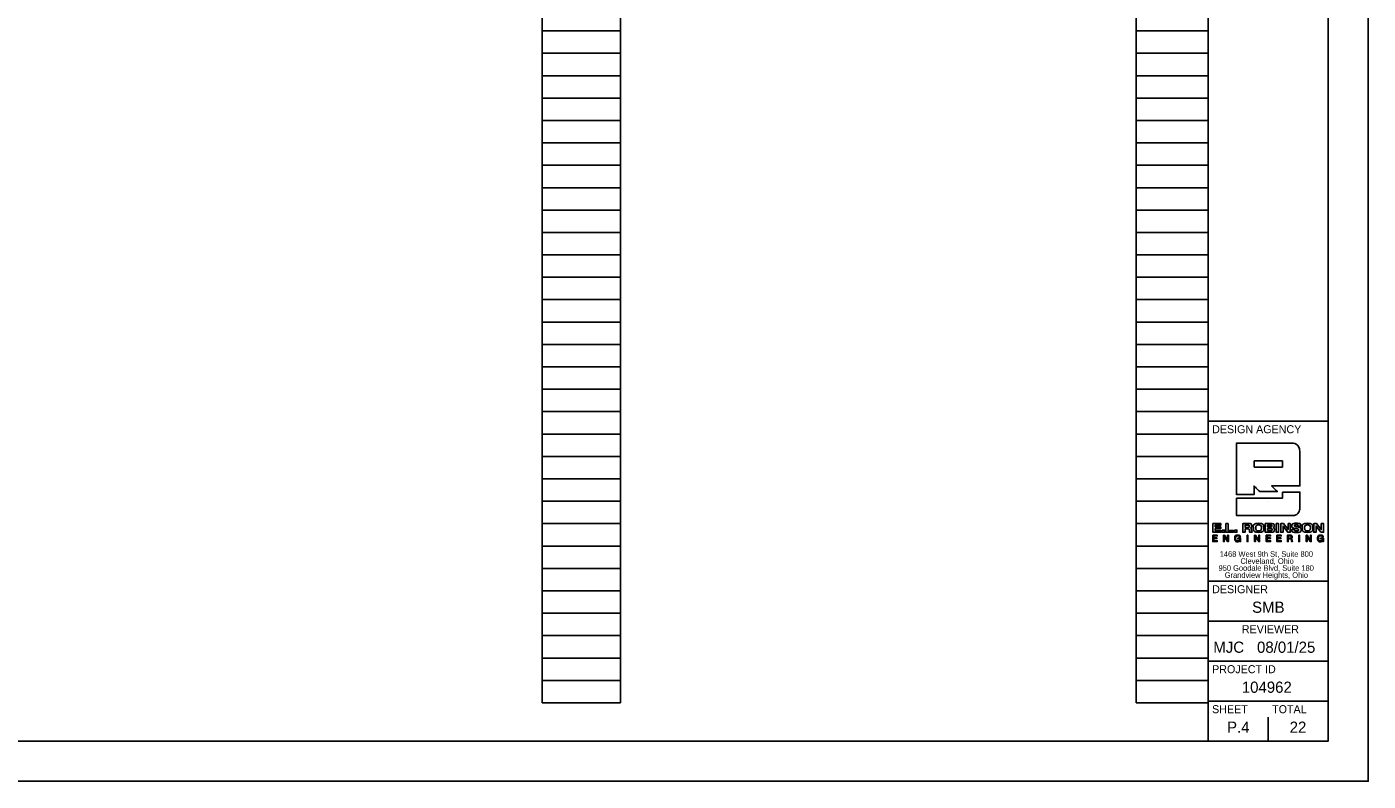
# Model space of a CAD drawing. Extents: x 0 to 34, y 0 to 22.
# Drawn here: x 17.24 to 34, y 0 to 9.43 of the extents above; entities that cross this region are included whole.
import ezdxf

# ---------------------------------------------------------------- set-up
doc = ezdxf.new("R2010")
doc.units = 0
for name, color, linetype in [('SH_Border', 7, 'Continuous'), ('SH_Cut_Line', 7, 'Continuous'), ('SH_Data', 7, 'Continuous')]:
    doc.layers.add(name, color=color, linetype=linetype)

msp = doc.modelspace()

# ---------------------------------------------------------------- linework, layer by layer
at = {"layer": 'SH_Border'}
for p, q in [((32, 0.5), (32, 21.5)), ((32, 4.5), (33.5, 4.5)), ((32, 2.5), (33.5, 2.5)), ((32, 2), (33.5, 2)), ((32, 1.5), (33.5, 1.5)), ((32, 1), (33.5, 1))]:
    msp.add_line(p, q, dxfattribs=at)
msp.add_lwpolyline([(1.5, 21.5), (33.5, 21.5), (33.5, 0.5), (1.5, 0.5)], close=True, dxfattribs=at)
at = {"layer": 'SH_Cut_Line'}
msp.add_lwpolyline([(0, 0), (34, 0), (34, 22), (0, 22)], close=True, dxfattribs=at)
at = {"layer": 'SH_Data'}
for p, q in [((23.68, 0.98), (23.68, 21.14)), ((24.66, 0.98), (24.66, 21.14)), ((31.1, 0.98), (31.1, 21.14)), ((32, 0.98), (32, 21.14)), ((23.68, 9.38), (24.66, 9.38)), ((31.1, 9.38), (32, 9.38)), ((23.68, 9.1), (24.66, 9.1)), ((31.1, 9.1), (32, 9.1)), ((23.68, 8.82), (24.66, 8.82)), ((31.1, 8.82), (32, 8.82)), ((23.68, 8.54), (24.66, 8.54)), ((31.1, 8.54), (32, 8.54)), ((23.68, 8.26), (24.66, 8.26)), ((31.1, 8.26), (32, 8.26)), ((23.68, 7.98), (24.66, 7.98)), ((31.1, 7.98), (32, 7.98)), ((23.68, 7.7), (24.66, 7.7)), ((31.1, 7.7), (32, 7.7)), ((23.68, 7.42), (24.66, 7.42)), ((31.1, 7.42), (32, 7.42)), ((23.68, 7.14), (24.66, 7.14)), ((31.1, 7.14), (32, 7.14)), ((23.68, 6.86), (24.66, 6.86)), ((31.1, 6.86), (32, 6.86)), ((23.68, 6.58), (24.66, 6.58)), ((31.1, 6.58), (32, 6.58)), ((23.68, 6.3), (24.66, 6.3)), ((31.1, 6.3), (32, 6.3)), ((23.68, 6.02), (24.66, 6.02)), ((31.1, 6.02), (32, 6.02)), ((23.68, 5.74), (24.66, 5.74)), ((31.1, 5.74), (32, 5.74)), ((23.68, 5.46), (24.66, 5.46)), ((31.1, 5.46), (32, 5.46)), ((23.68, 5.18), (24.66, 5.18)), ((31.1, 5.18), (32, 5.18)), ((23.68, 4.9), (24.66, 4.9)), ((31.1, 4.9), (32, 4.9)), ((23.68, 4.62), (24.66, 4.62)), ((31.1, 4.62), (32, 4.62)), ((23.68, 4.34), (24.66, 4.34)), ((31.1, 4.34), (32, 4.34)), ((23.68, 4.06), (24.66, 4.06)), ((31.1, 4.06), (32, 4.06)), ((32.929, 4.003), (32.574, 4.003)), ((32.574, 4.003), (32.574, 3.925)), ((32.574, 3.925), (32.929, 3.925)), ((32.929, 3.925), (32.929, 4.003)), ((23.68, 3.78), (24.66, 3.78)), ((31.1, 3.78), (32, 3.78)), ((23.68, 3.5), (24.66, 3.5)), ((31.1, 3.5), (32, 3.5)), ((32.75, 3.5), (32.75, 3.5)), ((23.68, 3.22), (24.66, 3.22)), ((31.1, 3.22), (32, 3.22)), ((32.463, 3.201), (32.463, 3.173)), ((32.743, 3.202), (32.743, 3.178)), ((32.743, 3.159), (32.743, 3.133)), ((33.001, 3.066), (33.001, 3.039)), ((33.001, 3.039), (33.023, 3.039)), ((23.68, 2.94), (24.66, 2.94)), ((31.1, 2.94), (32, 2.94)), ((23.68, 2.66), (24.66, 2.66)), ((31.1, 2.66), (32, 2.66)), ((23.68, 2.38), (24.66, 2.38)), ((31.1, 2.38), (32, 2.38)), ((23.68, 2.1), (24.66, 2.1)), ((31.1, 2.1), (32, 2.1)), ((23.68, 1.82), (24.66, 1.82)), ((31.1, 1.82), (32, 1.82)), ((23.68, 1.54), (24.66, 1.54)), ((31.1, 1.54), (32, 1.54)), ((23.68, 1.26), (24.66, 1.26)), ((31.1, 1.26), (32, 1.26)), ((23.68, 0.98), (24.66, 0.98)), ((31.1, 0.98), (32, 0.98)), ((32.375, 0.675), (32.375, 0.675)), ((32.75, 0.5), (32.75, 0.8))]:
    msp.add_line(p, q, dxfattribs=at)
for points in [[(32.06, 3.221), (32.161, 3.221), (32.161, 3.201), (32.089, 3.201), (32.089, 3.178), (32.158, 3.178), (32.158, 3.158), (32.089, 3.158), (32.089, 3.133), (32.162, 3.133), (32.162, 3.113), (32.06, 3.113), (32.06, 3.221)], [(32.22, 3.221), (32.249, 3.221), (32.249, 3.134), (32.316, 3.134), (32.316, 3.113), (32.22, 3.113), (32.22, 3.221)], [(32.851, 3.221), (32.881, 3.221), (32.881, 3.113), (32.851, 3.113), (32.851, 3.221)], [(32.999, 3.221), (33.027, 3.221), (33.027, 3.113), (32.995, 3.113), (32.936, 3.189), (32.936, 3.189), (32.936, 3.113), (32.907, 3.113), (32.907, 3.221), (32.941, 3.221), (32.999, 3.146), (32.999, 3.146), (32.999, 3.221)], [(33.413, 3.221), (33.442, 3.221), (33.442, 3.113), (33.41, 3.113), (33.35, 3.189), (33.35, 3.189), (33.35, 3.113), (33.321, 3.113), (33.321, 3.221), (33.356, 3.221), (33.413, 3.146), (33.413, 3.146), (33.413, 3.221)], [(32.059, 3.075), (32.114, 3.075), (32.114, 3.066), (32.07, 3.066), (32.07, 3.041), (32.111, 3.041), (32.111, 3.032), (32.07, 3.032), (32.07, 3.005), (32.114, 3.005), (32.114, 2.996), (32.059, 2.996), (32.059, 3.075)], [(32.175, 3.139), (32.205, 3.139), (32.205, 3.113), (32.175, 3.113), (32.175, 3.139)], [(32.191, 3.075), (32.203, 3.075), (32.244, 3.011), (32.244, 3.011), (32.244, 3.075), (32.254, 3.075), (32.254, 2.996), (32.243, 2.996), (32.202, 3.059), (32.201, 3.059), (32.201, 2.996), (32.191, 2.996), (32.191, 3.075)], [(32.331, 3.139), (32.361, 3.139), (32.361, 3.113), (32.331, 3.113), (32.331, 3.139)], [(32.487, 3.075), (32.498, 3.075), (32.498, 2.996), (32.487, 2.996), (32.487, 3.075)], [(32.581, 3.075), (32.592, 3.075), (32.633, 3.011), (32.633, 3.011), (32.633, 3.075), (32.643, 3.075), (32.643, 2.996), (32.632, 2.996), (32.591, 3.059), (32.591, 3.059), (32.591, 2.996), (32.581, 2.996), (32.581, 3.075)], [(32.726, 3.075), (32.781, 3.075), (32.781, 3.066), (32.737, 3.066), (32.737, 3.041), (32.778, 3.041), (32.778, 3.032), (32.737, 3.032), (32.737, 3.005), (32.781, 3.005), (32.781, 2.996), (32.726, 2.996), (32.726, 3.075)], [(32.859, 3.075), (32.913, 3.075), (32.913, 3.066), (32.869, 3.066), (32.869, 3.041), (32.91, 3.041), (32.91, 3.032), (32.869, 3.032), (32.869, 3.005), (32.913, 3.005), (32.913, 2.996), (32.859, 2.996), (32.859, 3.075)], [(33.133, 3.075), (33.143, 3.075), (33.143, 2.996), (33.133, 2.996), (33.133, 3.075)], [(33.226, 3.075), (33.237, 3.075), (33.279, 3.011), (33.279, 3.011), (33.279, 3.075), (33.289, 3.075), (33.289, 2.996), (33.277, 2.996), (33.236, 3.059), (33.236, 3.059), (33.236, 2.996), (33.226, 2.996), (33.226, 3.075)]]:
    msp.add_lwpolyline(points, dxfattribs=at)
for points, degree in [([(32.356, 3.583), (32.356, 3.586), (32.356, 4.224), (32.356, 4.227)], 2), ([(32.356, 4.227), (32.36, 4.227), (33.03, 4.227), (33.034, 4.227), (33.096, 4.227), (33.147, 4.177), (33.147, 4.114)], 3), ([(33.147, 4.114), (33.147, 4.112), (33.147, 3.694), (33.147, 3.692)], 2), ([(32.645, 3.621), (32.645, 3.621), (32.574, 3.691), (32.574, 3.692)], 2), ([(32.574, 3.692), (32.574, 3.691), (32.574, 3.583), (32.574, 3.583)], 2), ([(33.147, 3.692), (33.145, 3.692), (32.795, 3.692), (32.793, 3.692)], 2), ([(32.793, 3.692), (32.793, 3.691), (32.866, 3.621), (32.866, 3.621)], 2), ([(32.929, 3.615), (32.929, 3.615), (33.147, 3.615), (33.147, 3.615), (33.147, 3.615), (33.147, 3.433), (33.147, 3.433), (33.147, 3.37), (33.096, 3.32), (33.034, 3.32), (33.034, 3.32), (32.356, 3.32), (32.356, 3.32), (32.356, 3.32), (32.356, 3.537), (32.356, 3.537), (32.356, 3.537), (32.929, 3.537), (32.929, 3.537), (32.929, 3.537), (32.929, 3.615), (32.929, 3.615)], 3), ([(32.574, 3.583), (32.573, 3.583), (32.357, 3.583), (32.356, 3.583)], 2), ([(32.866, 3.621), (32.865, 3.621), (32.646, 3.621), (32.645, 3.621)], 2), ([(32.433, 3.113), (32.433, 3.113), (32.433, 3.221), (32.433, 3.221)], 2), ([(32.433, 3.221), (32.433, 3.221), (32.512, 3.221), (32.512, 3.221), (32.542, 3.221), (32.545, 3.203), (32.546, 3.192)], 3), ([(32.463, 3.173), (32.463, 3.173), (32.502, 3.173), (32.502, 3.173), (32.508, 3.173), (32.516, 3.177), (32.516, 3.187), (32.516, 3.198), (32.507, 3.201), (32.5, 3.201), (32.5, 3.201), (32.463, 3.201), (32.463, 3.201), (32.463, 3.201), (32.463, 3.173), (32.463, 3.173)], 3), ([(32.463, 3.173), (32.476, 3.173), (32.489, 3.173), (32.508, 3.173), (32.516, 3.177), (32.516, 3.198), (32.507, 3.201), (32.488, 3.201), (32.475, 3.201), (32.463, 3.201)], 3), ([(32.546, 3.192), (32.544, 3.179), (32.542, 3.17), (32.53, 3.166)], 2), ([(32.631, 3.11), (32.573, 3.11), (32.567, 3.145), (32.565, 3.167), (32.564, 3.19), (32.573, 3.224), (32.631, 3.224)], 3), ([(32.631, 3.13), (32.658, 3.13), (32.667, 3.15), (32.667, 3.167), (32.667, 3.184), (32.658, 3.204), (32.631, 3.204), (32.604, 3.204), (32.595, 3.184), (32.595, 3.167), (32.595, 3.15), (32.604, 3.13), (32.631, 3.13)], 3), ([(32.631, 3.204), (32.604, 3.204), (32.595, 3.184), (32.595, 3.167), (32.595, 3.15), (32.604, 3.13), (32.631, 3.13)], 3), ([(32.631, 3.224), (32.69, 3.224), (32.695, 3.189), (32.697, 3.167), (32.699, 3.144), (32.69, 3.11), (32.631, 3.11)], 3), ([(32.631, 3.13), (32.658, 3.13), (32.667, 3.15), (32.667, 3.167), (32.667, 3.184), (32.658, 3.204), (32.631, 3.204)], 3), ([(32.714, 3.113), (32.714, 3.113), (32.714, 3.221), (32.714, 3.221)], 2), ([(32.714, 3.221), (32.714, 3.221), (32.795, 3.221), (32.795, 3.221)], 2), ([(32.743, 3.178), (32.743, 3.178), (32.784, 3.178), (32.784, 3.178), (32.791, 3.178), (32.796, 3.182), (32.796, 3.19), (32.796, 3.197), (32.793, 3.202), (32.78, 3.202), (32.78, 3.202), (32.743, 3.202), (32.743, 3.202), (32.743, 3.202), (32.743, 3.178), (32.743, 3.178)], 3), ([(32.743, 3.178), (32.757, 3.178), (32.771, 3.178), (32.791, 3.181), (32.791, 3.183), (32.792, 3.197), (32.793, 3.202), (32.768, 3.202), (32.756, 3.202), (32.743, 3.202)], 3), ([(32.795, 3.221), (32.81, 3.218), (32.826, 3.214), (32.826, 3.194)], 2), ([(32.826, 3.194), (32.824, 3.186), (32.822, 3.175), (32.812, 3.172)], 2), ([(33.126, 3.19), (33.124, 3.204), (33.111, 3.206), (33.099, 3.206), (33.087, 3.206), (33.079, 3.2), (33.079, 3.193), (33.079, 3.187), (33.084, 3.184), (33.091, 3.183), (33.091, 3.183), (33.128, 3.177), (33.128, 3.177), (33.148, 3.173), (33.163, 3.166), (33.163, 3.146), (33.163, 3.126), (33.149, 3.11), (33.107, 3.11), (33.08, 3.11), (33.046, 3.113), (33.045, 3.147), (33.045, 3.147), (33.079, 3.147), (33.079, 3.147), (33.079, 3.132), (33.094, 3.129), (33.107, 3.129), (33.121, 3.129), (33.13, 3.134), (33.13, 3.143), (33.13, 3.151), (33.123, 3.154), (33.112, 3.155), (33.112, 3.155), (33.085, 3.16), (33.085, 3.16), (33.066, 3.162), (33.047, 3.168), (33.047, 3.19), (33.047, 3.215), (33.067, 3.224), (33.101, 3.224), (33.124, 3.224), (33.157, 3.221), (33.159, 3.19), (33.159, 3.19), (33.126, 3.19), (33.126, 3.19)], 3), ([(33.242, 3.11), (33.183, 3.11), (33.178, 3.145), (33.176, 3.167), (33.174, 3.19), (33.183, 3.224), (33.242, 3.224)], 3), ([(33.242, 3.13), (33.269, 3.13), (33.278, 3.15), (33.278, 3.167), (33.278, 3.184), (33.269, 3.204), (33.242, 3.204), (33.215, 3.204), (33.205, 3.184), (33.205, 3.167), (33.205, 3.15), (33.215, 3.13), (33.242, 3.13)], 3), ([(33.242, 3.204), (33.215, 3.204), (33.205, 3.184), (33.205, 3.167), (33.205, 3.15), (33.215, 3.13), (33.242, 3.13)], 3), ([(33.242, 3.224), (33.3, 3.224), (33.306, 3.189), (33.308, 3.167), (33.309, 3.144), (33.3, 3.11), (33.242, 3.11)], 3), ([(33.242, 3.13), (33.269, 3.13), (33.278, 3.15), (33.278, 3.167), (33.278, 3.184), (33.269, 3.204), (33.242, 3.204)], 3), ([(32.396, 3.006), (32.39, 2.998), (32.38, 2.994), (32.37, 2.994), (32.347, 2.994), (32.333, 3.014), (32.333, 3.034), (32.333, 3.057), (32.346, 3.077), (32.37, 3.077), (32.388, 3.077), (32.401, 3.069), (32.404, 3.051), (32.404, 3.051), (32.394, 3.051), (32.394, 3.051), (32.392, 3.062), (32.382, 3.068), (32.37, 3.068), (32.351, 3.068), (32.344, 3.051), (32.344, 3.034), (32.344, 3.018), (32.353, 3.003), (32.37, 3.003), (32.387, 3.003), (32.396, 3.015), (32.396, 3.029), (32.396, 3.029), (32.371, 3.029), (32.371, 3.029), (32.371, 3.029), (32.371, 3.038), (32.371, 3.038), (32.371, 3.038), (32.405, 3.038), (32.405, 3.038), (32.405, 3.038), (32.405, 2.996), (32.405, 2.996), (32.405, 2.996), (32.398, 2.996), (32.398, 2.996), (32.398, 2.996), (32.396, 3.006), (32.396, 3.006)], 3), ([(32.463, 3.113), (32.462, 3.113), (32.433, 3.113), (32.433, 3.113)], 2), ([(32.499, 3.153), (32.499, 3.153), (32.463, 3.153), (32.463, 3.153)], 2), ([(32.463, 3.153), (32.463, 3.152), (32.463, 3.113), (32.463, 3.113)], 2), ([(32.518, 3.113), (32.516, 3.118), (32.516, 3.122), (32.516, 3.134), (32.515, 3.149), (32.508, 3.15), (32.499, 3.153)], 3), ([(32.55, 3.113), (32.55, 3.113), (32.518, 3.113), (32.518, 3.113)], 2), ([(32.53, 3.166), (32.53, 3.166), (32.53, 3.165), (32.53, 3.165)], 2), ([(32.53, 3.165), (32.543, 3.163), (32.544, 3.147), (32.544, 3.136)], 2), ([(32.544, 3.136), (32.544, 3.131), (32.548, 3.119), (32.55, 3.113)], 2), ([(32.829, 3.145), (32.827, 3.132), (32.824, 3.113), (32.791, 3.113), (32.791, 3.113), (32.714, 3.113), (32.714, 3.113)], 3), ([(32.743, 3.133), (32.743, 3.133), (32.787, 3.133), (32.787, 3.133), (32.796, 3.133), (32.8, 3.139), (32.8, 3.146), (32.8, 3.155), (32.794, 3.159), (32.784, 3.159), (32.784, 3.159), (32.743, 3.159), (32.743, 3.159), (32.743, 3.159), (32.743, 3.133), (32.743, 3.133)], 3), ([(32.743, 3.133), (32.758, 3.133), (32.772, 3.133), (32.796, 3.133), (32.8, 3.139), (32.8, 3.155), (32.794, 3.159), (32.77, 3.159), (32.757, 3.159), (32.743, 3.159)], 3), ([(32.812, 3.172), (32.812, 3.172), (32.812, 3.172), (32.812, 3.172)], 2), ([(32.812, 3.172), (32.824, 3.17), (32.827, 3.156), (32.829, 3.145)], 2), ([(32.991, 3.075), (32.991, 3.075), (33.027, 3.075), (33.028, 3.075), (33.042, 3.075), (33.051, 3.067), (33.051, 3.054)], 3), ([(32.991, 2.996), (32.991, 2.997), (32.991, 3.074), (32.991, 3.075)], 2), ([(33.023, 3.039), (33.033, 3.039), (33.041, 3.041), (33.041, 3.052), (33.041, 3.06), (33.037, 3.066), (33.027, 3.066), (33.027, 3.066), (33.001, 3.066), (33.001, 3.066), (33.001, 3.066), (33.001, 3.039), (33.001, 3.039), (33.001, 3.039), (33.023, 3.039), (33.023, 3.039)], 3), ([(33.023, 3.039), (33.033, 3.039), (33.041, 3.041), (33.041, 3.06), (33.037, 3.066), (33.018, 3.066), (33.01, 3.066), (33.001, 3.066)], 3), ([(33.04, 3.016), (33.038, 3.023), (33.037, 3.03), (33.027, 3.03), (33.027, 3.03), (33.001, 3.03), (33.001, 3.03)], 3), ([(33.001, 3.03), (33.001, 3.03), (33.001, 2.996), (33.001, 2.996)], 2), ([(33.051, 3.054), (33.049, 3.045), (33.047, 3.037), (33.038, 3.034)], 2), ([(33.038, 3.034), (33.038, 3.034), (33.038, 3.034), (33.038, 3.034)], 2), ([(33.038, 3.034), (33.044, 3.029), (33.047, 3.025), (33.048, 3.018)], 2), ([(33.048, 3.018), (33.049, 3.01), (33.052, 3.002), (33.054, 2.996)], 2), ([(33.43, 3.006), (33.424, 2.998), (33.414, 2.994), (33.405, 2.994), (33.382, 2.994), (33.368, 3.014), (33.368, 3.034), (33.368, 3.057), (33.38, 3.077), (33.405, 3.077), (33.422, 3.077), (33.436, 3.069), (33.439, 3.051), (33.439, 3.051), (33.429, 3.051), (33.429, 3.051), (33.426, 3.062), (33.417, 3.068), (33.405, 3.068), (33.386, 3.068), (33.378, 3.051), (33.378, 3.034), (33.378, 3.018), (33.388, 3.003), (33.405, 3.003), (33.421, 3.003), (33.431, 3.015), (33.43, 3.029), (33.43, 3.029), (33.405, 3.029), (33.405, 3.029), (33.405, 3.029), (33.405, 3.038), (33.405, 3.038), (33.405, 3.038), (33.44, 3.038), (33.44, 3.038), (33.44, 3.038), (33.44, 2.996), (33.44, 2.996), (33.44, 2.996), (33.433, 2.996), (33.433, 2.996), (33.433, 2.996), (33.43, 3.006), (33.43, 3.006)], 3), ([(33.001, 2.996), (33.001, 2.996), (32.991, 2.996), (32.991, 2.996)], 2), ([(33.043, 2.996), (33.042, 3), (33.041, 3.008), (33.04, 3.016)], 2), ([(33.054, 2.996), (33.054, 2.996), (33.043, 2.996), (33.043, 2.996)], 2)]:
    msp.add_open_spline(points, degree=degree, dxfattribs=at)

# ---------------------------------------------------------------- texts
for s, height, p in [('DESIGN AGENCY', 0.1, (32.05, 4.35)), ('1468 West 9th St, Suite 800', 0.07, (32.145, 2.805)), ('950 Goodale Blvd, Suite 180', 0.07, (32.13, 2.63)), ('Cleveland, Ohio', 0.07, (32.404, 2.717)), ('Grandview Heights, Ohio', 0.07, (32.208, 2.542)), ('DESIGNER', 0.1, (32.05, 2.35)), ('SMB', 0.14, (32.55, 2.105)), ('REVIEWER', 0.1, (32.422, 1.85)), ('MJC', 0.14, (32.065, 1.605)), ('08/01/25', 0.14, (32.611, 1.605)), ('PROJECT ID', 0.1, (32.05, 1.35)), ('104962', 0.14, (32.421, 1.105)), ('SHEET', 0.1, (32.05, 0.85)), ('TOTAL', 0.1, (32.8, 0.85)), ('P.4', 0.14, (32.237, 0.605)), ('22', 0.14, (33.019, 0.605))]:
    msp.add_text(s, height=height, dxfattribs=at).set_placement(p)

doc.saveas('drawing.dxf')
